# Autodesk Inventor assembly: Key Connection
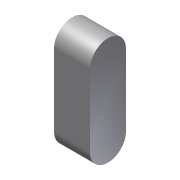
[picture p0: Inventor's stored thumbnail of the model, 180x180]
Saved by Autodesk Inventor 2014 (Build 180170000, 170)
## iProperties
Created: 2011-01
Part Number: Key Connection
Document SubType Name: Assembly
Designer: Beta-8540w
ClientObjectVersion: 1
Author: Beta-8540w
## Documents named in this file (2)
- C:\Inventor 2014 Essentials\Assemblies\Chapter 09\Design Accelerators\Key Connection c09-01.iam
- C:\Inventor 2014 Essentials\Content Center Files\en-US\DIN 6885  A\DIN 6885 - A 4 x 4 x 12.ipt
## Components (1 placed, 1 different names)
1. DIN 6885 A A 4 x 4 x 12:1
